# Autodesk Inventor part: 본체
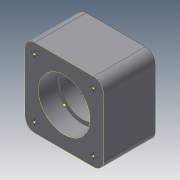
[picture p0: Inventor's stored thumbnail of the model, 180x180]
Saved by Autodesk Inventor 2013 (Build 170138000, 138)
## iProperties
Created: 2020-11
Part Number: 본체
Material: Generic
Document SubType Name: Modeling
Designer: 19
Density: 1 g/cm^3
Author: 19
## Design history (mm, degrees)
sketch "스케치1"
  geometry: L1 (-32, -32)-(32, -32); L2 (32, -32)-(32, 32); L3 (32, 32)-(-32, 32); L4 (-32, 32)-(-32, -32); L5 (-32, -32)-(32, 32); L6 (32, -32)-(-32, 32); 1 further point
  constraints: 12 end point, 2 midpoint, 2 parallel, 1 horizontal, 1 perpendicular
  dimensions: "d0" = 64 distance of L3.end L2.end; "d1" = 64 distance of L2.end L1.end
extrude "돌출1" new body sketch "스케치1" stored distance "d2" = 42; taper "d3" = 0 deg
sketch "스케치2"
  geometry: C1 r 21 at (0, 0); 1 further point
  constraints: 1 centre point, 1 coincident
  dimensions: "d4" = 42 diameter of C1
extrude "돌출2" cut sketch "스케치2" distance "d5" = 15; taper "d6" = 0 deg
sketch "스케치3"
  geometry: C1 r 21 at (0, 0); 1 further point
  constraints: 1 centre point, 1 coincident
  dimensions: "d7" = 42 diameter of C1
extrude "돌출3" cut sketch "스케치3" distance "d8" = 15; taper "d9" = 0 deg
sketch "스케치4"
  geometry: C1 r 21 at (0, 0) reference; C2 r 18 at (0, 0)
  constraints: 1 centre point, 1 coincident
  dimensions: "d10" = 36 diameter of C2
extrude "돌출4" cut sketch "스케치4" stored distance "d11" = 15; taper "d12" = 0 deg
fillet "모깎기1" dims "d13" = 8
sketch "스케치5"
  geometry: L1 (-24, -32)-(24, -32) reference; L2 (32, -24)-(32, 24) reference; L3 (24, 32)-(-24, 32) reference; L4 (-32, 24)-(-32, -24) reference; C1 r 21 at (0, 0) reference; A1 r 8 centre (-24, -24) between (-32, -24) and (-24, -32) reference; A2 r 8 centre (24, -24) between (24, -32) and (32, -24) reference; A3 r 8 centre (24, 24) between (32, 24) and (24, 32) reference; A4 r 8 centre (-24, 24) between (-24, 32) and (-32, 24) reference; 4 further points
  constraints: 4 coincident
node "솔리드1"
